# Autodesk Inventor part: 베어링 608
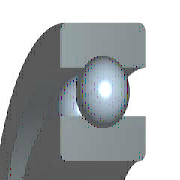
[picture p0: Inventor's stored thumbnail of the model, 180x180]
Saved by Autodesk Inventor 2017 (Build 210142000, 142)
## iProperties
IsCustomPart: 1
Created: 2012-02
Part Number: 베어링 608
Material: 강철, 연강
Description: 깊은 그루브 볼 베어링
Document SubType Name: Modeling
Standard: KS B 2023
Designer: mduedu
Standards Organization: KS
Language: ko-KR
Size Designation: 608 - 8 x 22 x 7
Categories: <MemberInstance><Categories><Category DisplayName="샤프트 부품" InternalName="7f7aeb1f-a693-4053-b835-cee3144e0d98" Mnemonic="SHFT"><Category DisplayName="베어링" Inter
Density: 1 g/cm^3
Appearance: 노란색
Author: mduedu
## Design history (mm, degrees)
sketch "스케치" dims "d0" = 3.64 (= -0.26 x WD + 0.26 x BD)
  geometry: L1 (1.68, 7.5)-(5.32, 7.5); L2 (3.5, 7.5)-(3.5, 5.68); L3 (3.5, 7.5)-(3.5, 9.32); L4 (2.148, 6.282)-(0, 6.282); L5 (0, 4)-(7, 4); L6 (2.148, 8.718)-(0, 8.718); L7 (0, 11)-(7, 11); L8 (7, 4)-(7, 6.282); L9 (4.852, 6.282)-(7, 6.282); L10 (4.852, 8.718)-(7, 8.718); L11 (7, 11)-(7, 8.718); L12 (-1.4, 0)-(8.4, 0) reference; L13 (0, -0.3)-(0, 5.3) reference
  constraints: 22 end point, 4 point on line, 2 collinear, 2 perpendicular, 2 symmetric about line, 1 midpoint, 1 parallel, 14 other
  dimensions: "d9" = 8 diameter of L5 L12 (= WD); "d11" = 22 diameter of L7 L12 (= BD); "d12" = 7 distance between parallel lines of L8 L13 (= KB); "d13" = 12.564 diameter of L9 L12 (= 0.326 x BD + 0.674 x WD)
revolve "본체" stored, may be unused: angle "d6" = 90 deg
revolve "볼" stored, may be unused: angle "d7" = 90 deg
pattern_circular "IDS_ARRAYBALL[SIMPL:T]" dims angle "d3" = 360 deg
body "Solid1"
fillet "모깎기1" dims "d1" = 0.3 (= KRS)
other parameters: "WD" = 8 [user parameter; used in 5 equation terms], "BD" = 22 [user parameter; used in 5 equation terms], "KB" = 7 [user parameter; used in 1 equation term], "KRS" = 0.3 [user parameter; used in 1 equation term], "d4" = 0, "d5" = 0, "d8" = 0, "d14" = 0, "d15" = 0, "BBA" = 0 [user parameter], "BC0" = 1370000 [user parameter], "BC" = 3250000 [user parameter], "BR" = 11 (= 0.5 x BD) [user parameter], "WR" = 4 (= 0.5 x WD) [user parameter]
